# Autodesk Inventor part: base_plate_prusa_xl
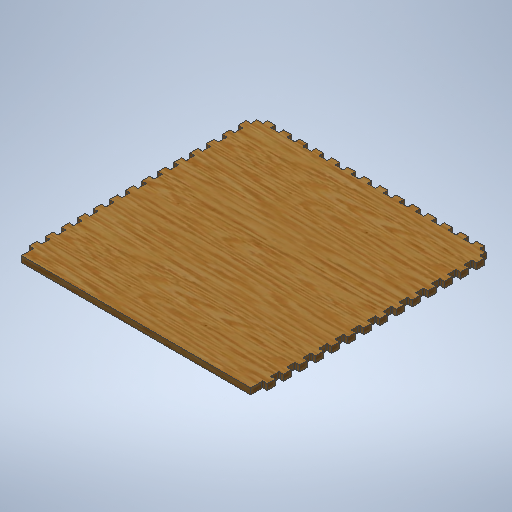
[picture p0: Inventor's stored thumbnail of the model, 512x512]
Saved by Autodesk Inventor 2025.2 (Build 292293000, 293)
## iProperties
Created: 2024-11
Part Number: base_plate_prusa_xl
Material: Plywood, Finish
Document SubType Name: Modeling
Designer: BennF
Density: 0.552 g/cm^3
Appearance: Plywood - New
Author: BennF
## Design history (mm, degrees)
sketch "Sketch2"
  geometry: L1 (-342, 351)-(342, 351); L2 (342, 351)-(342, -351); L3 (342, -351)-(-342, -351); L4 (-342, -351)-(-342, 351); 3 further points
  constraints: 8 end point, 2 midpoint, 2 parallel, 1 horizontal, 1 horizontal alignment, 1 perpendicular, 1 vertical alignment
  dimensions: "d0" = 684 distance of L1.start L1.end (= prusa_xl_shelf_wide); "d1" = 702 distance of L3.end L1.start (= prusa_xl_shelf_depth)
extrude "base_material" new body sketch "Sketch2" distance "d2" = 18 (= thickness); taper "d3" = 0 deg
sketch "Sketch3"
  geometry: L1 (-342, 351)-(-342, -351) reference; L2 (-342, -314.9)-(-355.5, -314.9); L3 (-355.5, -314.9)-(-355.5, -291.1); L4 (-355.5, -291.1)-(-342, -291.1); L5 (-342, -351)-(342, -351) reference; L6 (-355.5, -243.1)-(-342, -243.1); L7 (-355.5, -266.9)-(-355.5, -243.1); L8 (-342, -266.9)-(-355.5, -266.9); L9 (-355.5, -195.1)-(-342, -195.1); L10 (-355.5, -218.9)-(-355.5, -195.1); L11 (-342, -218.9)-(-355.5, -218.9); L12 (-355.5, -147.1)-(-342, -147.1); L13 (-355.5, -170.9)-(-355.5, -147.1); L14 (-342, -170.9)-(-355.5, -170.9); L15 (-355.5, -99.1)-(-342, -99.1); L16 (-355.5, -122.9)-(-355.5, -99.1); L17 (-342, -122.9)-(-355.5, -122.9); L18 (-355.5, -51.1)-(-342, -51.1); L19 (-355.5, -74.9)-(-355.5, -51.1); L20 (-342, -74.9)-(-355.5, -74.9); L21 (-355.5, -3.1)-(-342, -3.1); L22 (-355.5, -26.9)-(-355.5, -3.1); L23 (-342, -26.9)-(-355.5, -26.9); L24 (-355.5, 44.9)-(-342, 44.9); L25 (-355.5, 21.1)-(-355.5, 44.9); L26 (-342, 21.1)-(-355.5, 21.1); L27 (-355.5, 92.9)-(-342, 92.9); L28 (-355.5, 69.1)-(-355.5, 92.9); L29 (-342, 69.1)-(-355.5, 69.1); L30 (-355.5, 140.9)-(-342, 140.9); L31 (-355.5, 117.1)-(-355.5, 140.9); L32 (-342, 117.1)-(-355.5, 117.1); L33 (-355.5, 188.9)-(-342, 188.9); L34 (-355.5, 165.1)-(-355.5, 188.9); L35 (-342, 165.1)-(-355.5, 165.1); L36 (-355.5, 236.9)-(-342, 236.9); L37 (-355.5, 213.1)-(-355.5, 236.9); L38 (-342, 213.1)-(-355.5, 213.1); L39 (-355.5, 284.9)-(-342, 284.9); L40 (-355.5, 261.1)-(-355.5, 284.9); L41 (-342, 261.1)-(-355.5, 261.1); L42 (-355.5, 332.9)-(-342, 332.9); L43 (-355.5, 309.1)-(-355.5, 332.9); L44 (-342, 309.1)-(-355.5, 309.1); L45 (0, -351)-(0, 351); L46 (342, 351)-(342, -351); L47 (342, 351)-(342, -351); L48 (355.5, -3.1)-(342, -3.1); L49 (342, -26.9)-(355.5, -26.9); L50 (355.5, -170.9)-(355.5, -147.1); L51 (342, -170.9)-(355.5, -170.9); L52 (342, -314.9)-(355.5, -314.9); L53 (355.5, -314.9)-(355.5, -291.1); L54 (355.5, -291.1)-(342, -291.1); L55 (355.5, -266.9)-(355.5, -243.1); L56 (342, -266.9)-(355.5, -266.9); L57 (355.5, -243.1)-(342, -243.1); L58 (355.5, -218.9)-(355.5, -195.1); L59 (342, -218.9)-(355.5, -218.9); L60 (355.5, -195.1)-(342, -195.1); L61 (342, 21.1)-(355.5, 21.1); L62 (355.5, 44.9)-(342, 44.9); L63 (355.5, 21.1)-(355.5, 44.9); L64 (355.5, -26.9)-(355.5, -3.1)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; 83 further points
  constraints: 258 end point, 56 symmetric about line, 52 horizontal alignment, 52 parallel, 52 vertical alignment, 26 collinear, 4 point on line, 3 perpendicular, 2 vertical, 1 horizontal, 1 midpoint, 6 other
  dimensions: "d4" = 23.8 distance of L2.end L3.end (= finger_width - connection_clearence); "d5" = 13.5 distance of L3.end L4.end (= finger_depth - hidden_depth); "d6" = 36.1 distance between parallel lines of L5 L2 (= prusa_xl_depth_finger_distance + 0.5 x connection_clearence); "d9" = 48 distance of L3.end L6.start (= finger_distance); "d14" = 23.8 distance of L90.end L91.end (= finger_width - connection_clearence); "d15" = 13.5 distance of L91.end L92.end (= finger_depth - hidden_depth); "d16" = 31.6 distance between parallel lines of L90 L43 (= -hidden_depth + prusa_xl_width_finger_distance + 0.5 x connection_clearence); "d19" = 48 distance of L90.start L93.start (= finger_distance)
extrude "joints" join sketch "Sketch3" distance "d24" = 18 (= thickness); taper "d25" = 0 deg
sketch "Sketch4" dims "d26" = 6 (= dogbone_diameter)
  geometry: L1 (-342, -351)-(342, -351) reference; L2 (342, -351)-(342, -314.9) reference; L3 (342, -314.9)-(355.5, -314.9) reference; L4 (355.5, -314.9)-(355.5, -291.1) reference; L5 (355.5, -291.1)-(342, -291.1) reference; L6 (342, -291.1)-(342, -266.9) reference; L7 (342, -266.9)-(355.5, -266.9) reference; L8 (355.5, -266.9)-(355.5, -243.1) reference; L9 (355.5, -243.1)-(342, -243.1) reference; L10 (342, -243.1)-(342, -218.9) reference; L11 (342, -218.9)-(355.5, -218.9) reference; L12 (355.5, -218.9)-(355.5, -195.1) reference; L13 (355.5, -195.1)-(342, -195.1) reference; L14 (342, -195.1)-(342, -170.9) reference; L15 (342, -170.9)-(355.5, -170.9) reference; L16 (355.5, -170.9)-(355.5, -147.1) reference; L17 (355.5, -147.1)-(342, -147.1) reference; L18 (342, -147.1)-(342, -122.9) reference; L19 (342, -122.9)-(355.5, -122.9) reference; L20 (355.5, -122.9)-(355.5, -99.1) reference; L21 (355.5, -99.1)-(342, -99.1) reference; L22 (342, -99.1)-(342, -74.9) reference; L23 (342, -74.9)-(355.5, -74.9) reference; L24 (355.5, -74.9)-(355.5, -51.1) reference; L25 (355.5, -51.1)-(342, -51.1) reference; L26 (342, -51.1)-(342, -26.9) reference; L27 (342, -26.9)-(355.5, -26.9) reference; L28 (355.5, -26.9)-(355.5, -3.1) reference; L29 (355.5, -3.1)-(342, -3.1) reference; L30 (342, -3.1)-(342, 21.1) reference; L31 (342, 21.1)-(355.5, 21.1) reference; L32 (355.5, 21.1)-(355.5, 44.9) reference; L33 (355.5, 44.9)-(342, 44.9) reference; L34 (342, 44.9)-(342, 69.1) reference; L35 (342, 69.1)-(355.5, 69.1) reference; L36 (355.5, 69.1)-(355.5, 92.9) reference; L37 (355.5, 92.9)-(342, 92.9) reference; L38 (342, 92.9)-(342, 117.1) reference; L39 (342, 117.1)-(355.5, 117.1) reference; L40 (355.5, 117.1)-(355.5, 140.9) reference; L41 (355.5, 140.9)-(342, 140.9) reference; L42 (342, 140.9)-(342, 165.1) reference; L43 (342, 165.1)-(355.5, 165.1) reference; L44 (355.5, 165.1)-(355.5, 188.9) reference; L45 (355.5, 188.9)-(342, 188.9) reference; L46 (342, 188.9)-(342, 213.1) reference; L47 (342, 213.1)-(355.5, 213.1) reference; L48 (355.5, 213.1)-(355.5, 236.9) reference; L49 (355.5, 236.9)-(342, 236.9) reference; L50 (342, 236.9)-(342, 261.1) reference; L51 (342, 261.1)-(355.5, 261.1) reference; L52 (355.5, 261.1)-(355.5, 284.9) reference; L53 (355.5, 284.9)-(342, 284.9) reference; L54 (342, 284.9)-(342, 309.1) reference; L55 (342, 309.1)-(355.5, 309.1) reference; L56 (355.5, 309.1)-(355.5, 332.9) reference; L57 (355.5, 332.9)-(342, 332.9) reference; L58 (342, 332.9)-(342, 351) reference; L59 (342, 351)-(323.9, 351) reference; L60 (323.9, 351)-(323.9, 364.5) reference; L61 (323.9, 364.5)-(300.1, 364.5) reference; L62 (300.1, 364.5)-(300.1, 351) reference; L63 (300.1, 351)-(275.9, 351) reference; L64 (275.9, 351)-(275.9, 364.5) reference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; C1 r 3 at (344.121, 335.021); C2 r 3 at (344.121, 306.979); C3 r 3 at (344.121, 287.021); C4 r 3 at (344.121, 258.979); C5 r 3 at (344.121, 239.021); C6 r 3 at (344.121, 210.979); C7 r 3 at (344.121, 191.021); C8 r 3 at (344.121, 162.979); C9 r 3 at (344.121, 143.021); C10 r 3 at (344.121, 114.979); C11 r 3 at (344.121, 95.021); C12 r 3 at (344.121, 66.979); C13 r 3 at (344.121, 47.021); C14 r 3 at (344.121, 18.979); C15 r 3 at (344.121, -0.979); C16 r 3 at (344.121, -29.021); C17 r 3 at (344.121, -48.979); C18 r 3 at (344.121, -77.021); C19 r 3 at (344.121, -96.979); C20 r 3 at (344.121, -125.021); C21 r 3 at (344.121, -144.979); C22 r 3 at (344.121, -173.021); C23 r 3 at (344.121, -192.979); C24 r 3 at (344.121, -221.021); C25 r 3 at (344.121, -240.979); C26 r 3 at (344.121, -269.021); C27 r 3 at (344.121, -288.979); C28 r 3 at (344.121, -317.021); 113 further points
  constraints: 28 centre point, 28 horizontal, 28 symmetric about line, 28 vertical, 22 end point, 6 midpoint, 4 perpendicular, 4 point on line, 2 collinear, 2 horizontal alignment, 2 vertical alignment, 300 other
  dimensions: "d29" = 48 distance of point (-344.121, -317.021) point (-344.121, -269.021) (= finger_distance); "d36" = 48 distance of point (-326.021, 353.121) point (-278.021, 353.121) (= finger_distance)
extrude "dogbones" cut sketch "Sketch4" distance "d41" = 18 (= thickness); taper "d42" = 0 deg
body "Solid1"
node "Sketch Rectangular Pattern1" dims "d9" = 48 (= finger_distance), "d12" = 10
node "Sketch Rectangular Pattern2" dims "d19" = 48 (= finger_distance), "d22" = 10
node "Projected Loop1"
node "Sketch Rectangular Pattern3" dims "d29" = 48 (= finger_distance), "d32" = 10
node "Sketch Rectangular Pattern4" dims "d36" = 48 (= finger_distance), "d39" = 10
other parameters: "brett_stärke" = 18 [user parameter], "prusa_xl_shelf_depth" = 702 [user parameter; used in 1 equation term], "prusa_xl_shelf_wide" = 684 [user parameter; used in 1 equation term], "thickness" = 18 [user parameter; used in 3 equation terms], "prusa_xl_height" = 1005 [user parameter], "box_height_1" = 435 [user parameter], "box_height_2" = 235 [user parameter], "box_clearence_1" = 9.33333 [user parameter], "fingertip_depth" = 18 [user parameter], "finger_wide" = 24 [user parameter], "finger_depth" = 18 [user parameter; used in 2 equation terms], "fingertip_wide" = 6 [user parameter], "dogbone_angle" = 45 deg [user parameter], "dogbone_diameter" = 6 [user parameter; used in 1 equation term], "mill_bit" = 6 [user parameter], "prusa_xl_shelf_width" = 684 [user parameter], "finger_width" = 24 [user parameter; used in 2 equation terms], "finger_width_distance" = 48 [user parameter], "finger_distance" = 48 [user parameter; used in 4 equation terms], "prusa_xl_height_finger_distance" = 34.5 [user parameter], "prusa_xl_depth_finger_distance" = 36 [user parameter; used in 1 equation term], "prusa_xl_width_finger_distance" = 36 [user parameter; used in 1 equation term], "hidden_depth" = 4.5 [user parameter; used in 3 equation terms], "connection_clearence" = 0.2 [user parameter; used in 4 equation terms], "sla_width" = 1296 [user parameter], "back_distance" = 5 [user parameter], "back_connection_depth" = 5 [user parameter], "storage_width_2" = 322 [user parameter], "box_clearence_2" = 24.33333 [user parameter], "shelf_depth_finger_distance" = 39 [user parameter], "connection_back_clearence" = 0 [user parameter], "thickness_back" = 6 [user parameter], "finger_depth_middle" = 8 [user parameter], "box_height_3" = 285 [user parameter], "bowden_tube_diameter" = 4 [user parameter], "connector_width_offset" = 105 [user parameter], "connector_width" = 26 [user parameter], "connector_depth" = 16 [user parameter]
